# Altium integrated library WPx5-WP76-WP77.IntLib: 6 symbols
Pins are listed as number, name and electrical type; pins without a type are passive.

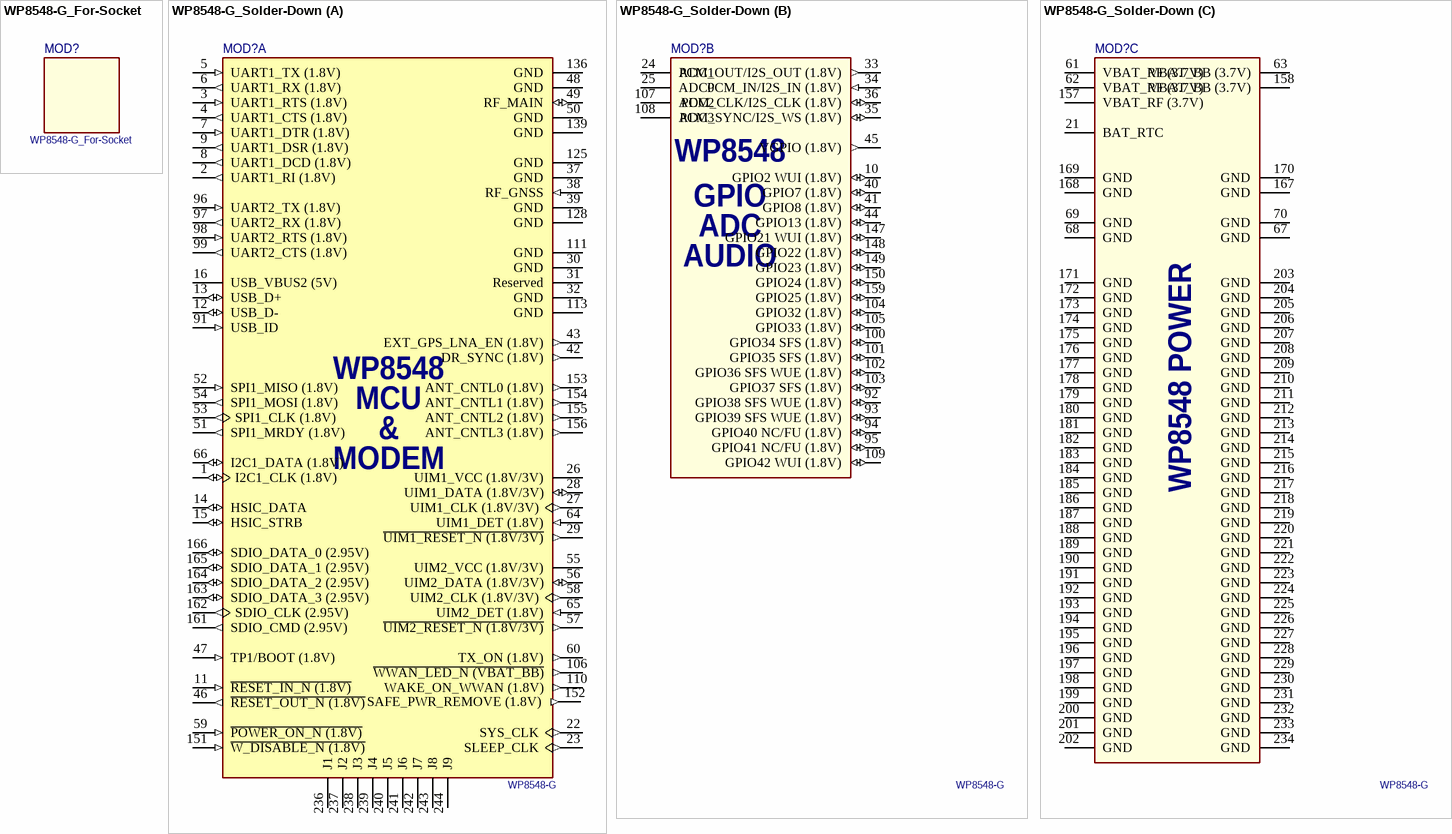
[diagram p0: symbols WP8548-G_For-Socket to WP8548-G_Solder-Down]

## WP8548-G_For-Socket
designator MOD?
Module Embedded MCU Wireless AirPrime WP8548 with GNSS; Manufacturer: Sierra Wireless; Description - Long: Sierra Wireless AirPrime WP8548 Smart Embedded Module with GNSS; Frequency GNSS: GPS 1575.42 ±1.023 MHz, GLONASS 1597.52–1605.92 MHz, Galileo 1575.42 ±2.046 MHz; Frequency GPRS/EDGE: GSM 850 Tx824–849 Rx869–894 MHz, E-GSM 900 Tx880–915 Rx925–960 MHz, DCS 1800 Tx1710–1785 Rx1805–1880 MHz, PCS 1900 Tx1850–1910 Rx1930–1990 MHz; Frequency UMTS: B1 Tx1920–1980 Rx2110–2170 MHz, B2 Tx1850–1910 Rx1930–1990 MHz, B5 Tx824–849 Rx869–894 MHz, B6 Tx830–840 Rx875–885 MHz, B8 Tx880–915 Rx925–960 MHz, B19 Tx830–845 Rx875–890 MHz; Functionality - MCU: 2 Cores: Qualcomm MDM8215 (QDSP6) for 2G/3G modem and ARM Cortex-A5 (550MHz) running Legato; Functionality - Radio: HSPA, WCDMA, Quad-band GSM, GPRS, EDGE (and GPS, GLONASS, Galileo on WP8548-G); Interface - ADC channels: 4x (ACD0-1 15-bit, ADC2-3 12-bit); Interface - Audio: 1x PCM (128/2048kHz) / I2S; Interface - GPIO: 20; Interface - HSIC (High-Speed Inter-Chip): 1x USB 2.0 Spec. V1.0; Interface - I2C: 1x 400kHz; Interface - SDIO: 1x 25MBps SD v2.0; Interface - SPI: 1x 4-wire @ 26MHz; Interface - UART: 1x 8-wire + 1x 4-wire @ 115200bps; Interface - UIM/SIM: 2x WCDMA & GSM11.11; Interface - USB: 1x 480Mbps; Memory - FLASH: 512MB; Memory - RAM: 256MB; Supply Current Max.: 3.0A; Supply Current Nom.: 1.0A; Supply Voltage Droop Max.: 250mV; Supply Voltage Max.: 4.3V; Supply Voltage Min.: 3.4V; Supply Voltage Nom.: 3.7V; Supply Voltage Ripple Max.: 100mVpp; Supply Voltage Transient Max.: 300mV; Temperature Max.: +85 deg C; Temperature Min.: -40 deg C; Release By: EDA Technologies; Release Revision: 1.2; Release Status: Released; Release History: 2017-03-14 1.2 Updated GPIO definitions. 2016-10-13 1.1 Updated_2016-09-05 1.0 First Release_2016-06-30 0.1 First Draft; Humidity Max.: 95% RH; Humidity Min.: 0% RH
footprint WP8548_For-Socket (LGA, 239 pads, Body 23.00 X 22.00 X 4.352mm)

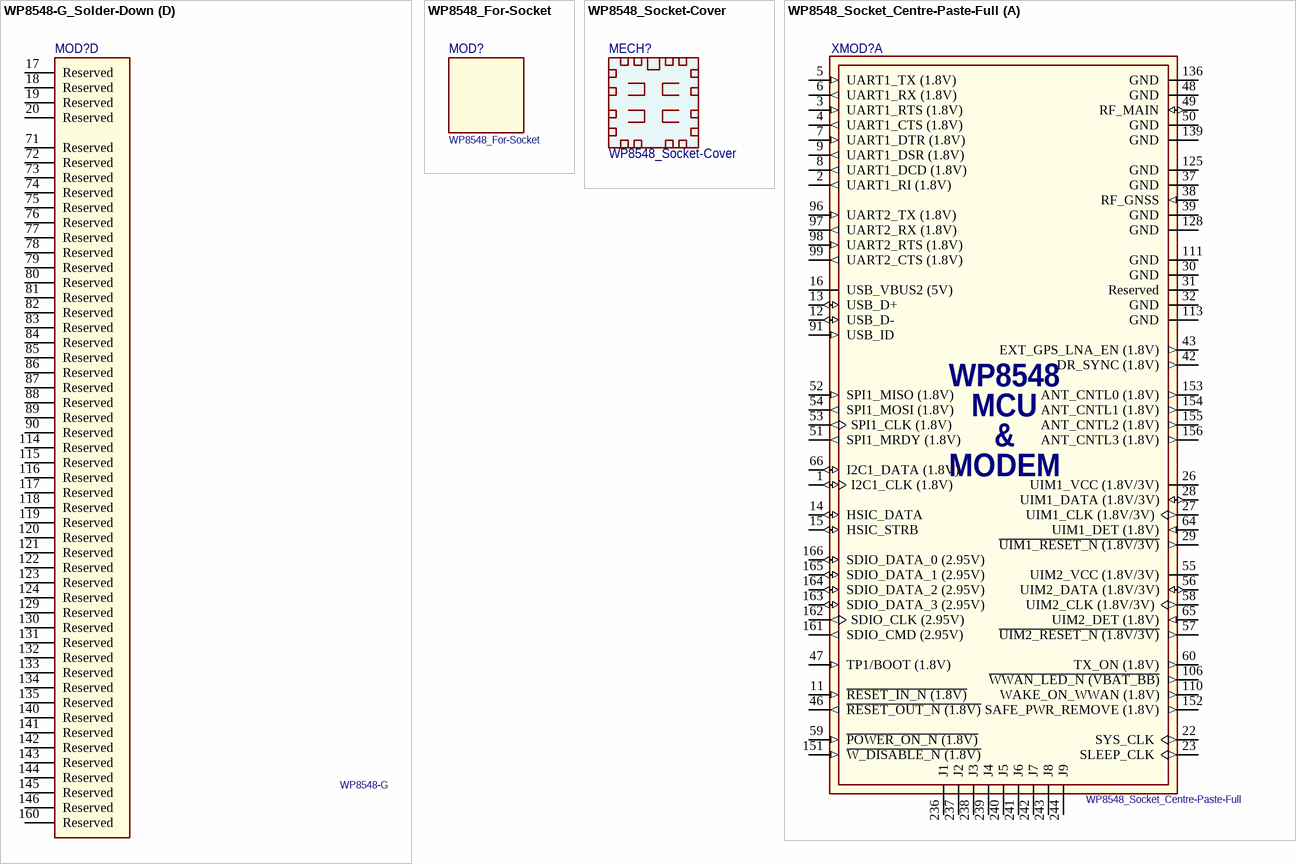
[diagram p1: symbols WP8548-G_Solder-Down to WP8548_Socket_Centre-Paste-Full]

## WP8548-G_Solder-Down
designator MOD?, comment WP8548-G
Module Embedded MCU Wireless AirPrime WP8548 with GNSS; Manufacturer: Sierra Wireless; Description - Long: Sierra Wireless AirPrime WP8548 Smart Embedded Module with GNSS; Frequency GNSS: GPS 1575.42 ±1.023 MHz, GLONASS 1597.52–1605.92 MHz, Galileo 1575.42 ±2.046 MHz; Frequency GPRS/EDGE: GSM 850 Tx824–849 Rx869–894 MHz, E-GSM 900 Tx880–915 Rx925–960 MHz, DCS 1800 Tx1710–1785 Rx1805–1880 MHz, PCS 1900 Tx1850–1910 Rx1930–1990 MHz; Frequency UMTS: B1 Tx1920–1980 Rx2110–2170 MHz, B2 Tx1850–1910 Rx1930–1990 MHz, B5 Tx824–849 Rx869–894 MHz, B6 Tx830–840 Rx875–885 MHz, B8 Tx880–915 Rx925–960 MHz, B19 Tx830–845 Rx875–890 MHz; Functionality - MCU: 2 Cores: Qualcomm MDM8215 (QDSP6) for 2G/3G modem and ARM Cortex-A5 (550MHz) running Legato; Functionality - Radio: HSPA, WCDMA, Quad-band GSM, GPRS, EDGE (and GPS, GLONASS, Galileo on WP8548-G); Interface - ADC channels: 4x (ACD0-1 15-bit, ADC2-3 12-bit); Interface - Audio: 1x PCM (128/2048kHz) / I2S; Interface - GPIO: 20; Interface - HSIC (High-Speed Inter-Chip): 1x USB 2.0 Spec. V1.0; Interface - I2C: 1x 400kHz; Interface - SDIO: 1x 25MBps SD v2.0; Interface - SPI: 1x 4-wire @ 26MHz; Interface - UART: 1x 8-wire + 1x 4-wire @ 115200bps; Interface - UIM/SIM: 2x WCDMA & GSM11.11; Interface - USB: 1x 480Mbps; Memory - FLASH: 512MB; Memory - RAM: 256MB; Supply Current Max.: 3.0A; Supply Current Nom.: 1.0A; Supply Voltage Droop Max.: 250mV; Supply Voltage Max.: 4.3V; Supply Voltage Min.: 3.4V; Supply Voltage Nom.: 3.7V; Supply Voltage Ripple Max.: 100mVpp; Supply Voltage Transient Max.: 300mV; Temperature Max.: +85 deg C; Temperature Min.: -40 deg C; Release By: EDA Technologies; Release Revision: 1.2; Release Status: Released; Release History: 2017-03-14 1.2 Updated GPIO definitions. 2016-10-13 1.1 Updated_2016-09-05 1.0 First Release_2016-06-30 0.1 First Draft; Humidity Max.: 95% RH; Humidity Min.: 0% RH
footprint WP8548_Solder-Down_LGA176_Large-Centre-Pad (LGA, 176 pads, Body 23.00 X 22.00 X 4.352mm, Large Centre Pad)
part A pins: 1 I2C1_CLK (1.8V) (io) "I2C Clock - 2k2 internal pull-up", 2 UART1_RI (1.8V) (out) "Ring Indicator. Signal incoming calls (voice and data), SMS, etc", 3 UART1_RTS (1.8V) (in) "Ready To Send, flow control", 4 UART1_CTS (1.8V) (out) "Clear To Send, flow control", 5 UART1_TX (1.8V) (in) "Transmit Data", 6 UART1_RX (1.8V) (out) "Receive Data", 7 UART1_DTR (1.8V) (in) "Data terminal ready. Prevents the AirPrime AirPrime WP8548 from entering sleep mode, switches between data mode and command mode, and wakes the module.", 8 UART1_DCD (1.8V) (out) "Data Carrier Detect. Signal data connection in progress", 9 UART1_DSR (1.8V) (out) "Data Set Ready. Signal UART interface is ON", 11 ~{RESET_IN_N (1.8V)} (in) "External Reset Input", 12 USB_D- (io) "Differential data interface negative", 13 USB_D+ (io) "Differential data interface positive", 14 HSIC_DATA (io) "HSIC data", 15 HSIC_STRB (io) "HSIC strobe signal", 16 USB_VBUS2 (5V) (power) "USB supply voltage input", 22 SYS_CLK (out) "19.2 MHz digital clock output", 23 SLEEP_CLK (out) "32.768 kHz digital clock output", 26 UIM1_VCC (1.8V/3V) (power) "Supply output", 27 UIM1_CLK (1.8V/3V) (out) "Clock", 28 UIM1_DATA (1.8V/3V) (io) "Data connection", 29 ~{UIM1_RESET_N (1.8V/3V)} (out) "Reset", 30 GND (power), 31 Reserved, 32 GND (power), 37 GND "GNSS Antenna Ground", 38 RF_GNSS (in) "GNSS Antenna Interface", 39 GND "GNSS Antenna Ground", 42 DR_SYNC (1.8V) (out) "GPS dead reckoning sync signal", 43 EXT_GPS_LNA_EN (1.8V) (out) "External GNSS LNA enable", 46 ~{RESET_OUT_N (1.8V)} (out) "Module reset peripheral device control", 47 TP1/BOOT (1.8V) (in) "Service (boot load)", 48 GND "Primary Antenna Ground", 49 RF_MAIN (io) "Primary Antenna Interface", 50 GND "Primary Antenna Ground", 51 SPI1_MRDY (1.8V) (out) "SPI Master Ready", 52 SPI1_MISO (1.8V) (in) "SPI Master Input/Slave Output", 53 SPI1_CLK (1.8V) (out) "SPI serial clock", 54 SPI1_MOSI (1.8V) (out) "SPI Master Output/Slave Input", 55 UIM2_VCC (1.8V/3V) (power) "Supply output", 56 UIM2_DATA (1.8V/3V) (io) "Data connection", 57 ~{UIM2_RESET_N (1.8V/3V)} (out) "Reset", 58 UIM2_CLK (1.8V/3V) (out) "Clock", 59 ~{POWER_ON_N (1.8V)} (in) "Power On control Signal", 60 TX_ON (1.8V) (out) "Tx activity indicator", 64 UIM1_DET (1.8V) (in) "Detect UIM", 65 UIM2_DET (1.8V) (in) "Detect UIM", 66 I2C1_DATA (1.8V) (io) "I2C Data - 2k2 internal pull-up", 91 USB_ID (in) "Used for USB_OTG", 96 UART2_TX (1.8V) (in) "Transmit data", 97 UART2_RX (1.8V) (out) "Receive data", 98 UART2_RTS (1.8V) (in) "Ready To Send, flow control", 99 UART2_CTS (1.8V) (out) "Clear To Send, flow control", 106 ~{WWAN_LED_N (VBAT_BB)} (out) "LED driver control", 110 WAKE_ON_WWAN (1.8V) (out) "Driven high to wake the hst when specific events occur", 111 GND (power), 113 GND (power), 125 GND "GNSS Antenna Ground", 128 GND "GNSS Antenna Ground", 136 GND "Primary Antenna Ground", 139 GND "Primary Antenna Ground", 151 ~{W_DISABLE_N (1.8V)} (in) "Wireless Disable", 152 SAFE_PWR_REMOVE (1.8V) (out) "Indicate to host that main DC power can be removed", 153 ANT_CNTL0 (1.8V) (out) "Customer-defined external switch control for tunable antennas", 154 ANT_CNTL1 (1.8V) (out) "Customer-defined external switch control for tunable antennas", 155 ANT_CNTL2 (1.8V) (out) "Customer-defined external switch control for tunable antennas", 156 ANT_CNTL3 (1.8V) (out) "Customer-defined external switch control for tunable antennas", 161 SDIO_CMD (2.95V) (out) "SDIO command", 162 SDIO_CLK (2.95V) (out) "SDIO clock", 163 SDIO_DATA_3 (2.95V) (io) "SDIO data bit 3", 164 SDIO_DATA_2 (2.95V) (io) "SDIO data bit 2", 165 SDIO_DATA_1 (2.95V) (io) "SDIO data bit 1", 166 SDIO_DATA_0 (2.95V) (io) "SDIO data bit 0", 236 J1 "Test Point", 237 J2 "Test Point", 238 J3 "Test Point", 239 J4 "Test Point", 240 J5 "Test Point", 241 J6 "Test Point", 242 J7 "Test Point", 243 J8 "Test Point", 244 J9 "Test Point"
part B pins: 10 GPIO2 WUI (1.8V) (io) "General purpose I/O (Wakeup Interrupt)", 24 ADC1 "Analog to Digital Converter", 25 ADC0 "Analog to Digital Converter", 33 PCM_OUT/I2S_OUT (1.8V) (out) "PCM/I2S Data Out", 34 PCM_IN/I2S_IN (1.8V) (in) "PCM/I2S Data In", 35 PCM_SYNC/I2S_WS (1.8V) (io) "PCM Sync/I2S Word Select", 36 PCM_CLK/I2S_CLK (1.8V) (io) "PCM/I2S Clock", 40 GPIO7 (1.8V) (io) "General purpose I/O", 41 GPIO8 (1.8V) (io) "General purpose I/O", 44 GPIO13 (1.8V) (io) "General purpose I/O", 45 VGPIO (1.8V) (out) "GPIO voltage output", 92 GPIO38 SFS WUE (1.8V) (io) "General purpose I/O (SYSFS Wakeup Event)", 93 GPIO39 SFS WUE (1.8V) (io) "General purpose I/O (SYSFS Wakeup Event)", 94 GPIO40 NC/FU (1.8V) (io) "General purpose I/O (Do Not Use/Future Use)", 95 GPIO41 NC/FU (1.8V) (io) "General purpose I/O (Do Not Use/Future Use)", 100 GPIO34 SFS (1.8V) (io) "General purpose I/O (SYSFS)", 101 GPIO35 SFS (1.8V) (io) "General purpose I/O (SYSFS)", 102 GPIO36 SFS WUE (1.8V) (io) "General purpose I/O (SYSFS Wakeup Event)", 103 GPIO37 SFS (1.8V) (io) "General purpose I/O (SYSFS)", 104 GPIO32 (1.8V) (io) "General purpose I/O", 105 GPIO33 (1.8V) (io) "General purpose I/O", 107 ADC2 "Analog to Digital Converter", 108 ADC3 "Analog to Digital Converter", 109 GPIO42 WUI (1.8V) (io) "General purpose I/O (Wakeup Interrupt)", 147 GPIO21 WUI (1.8V) (io) "General purpose I/O (Wakeup Interrupt)", 148 GPIO22 (1.8V) (io) "General purpose I/O", 149 GPIO23 (1.8V) (io) "General purpose I/O", 150 GPIO24 (1.8V) (io) "General purpose I/O", 159 GPIO25 (1.8V) (io) "General purpose I/O"
part C pins: 21 BAT_RTC (power) "Voltage input/Charging output", 61 VBAT_RF (3.7V) (power) "RF power supply", 62 VBAT_RF (3.7V) (power) "RF power supply", 63 VBAT_BB (3.7V) (power) "Baseband power supply", 67 GND (power), 68 GND (power), 69 GND (power), 70 GND (power), 157 VBAT_RF (3.7V) (power) "RF power supply", 158 VBAT_BB (3.7V) (power) "Baseband power supply", 167 GND (power), 168 GND (power), 169 GND (power), 170 GND (power), 171 GND (power), 172 GND (power), 173 GND (power), 174 GND (power), 175 GND (power), 176 GND (power), 177 GND (power), 178 GND (power), 179 GND (power), 180 GND (power), 181 GND (power), 182 GND (power), 183 GND (power), 184 GND (power), 185 GND (power), 186 GND (power), 187 GND (power), 188 GND (power), 189 GND (power), 190 GND (power), 191 GND (power), 192 GND (power), 193 GND (power), 194 GND (power), 195 GND (power), 196 GND (power), 197 GND (power), 198 GND (power), 199 GND (power), 200 GND (power), 201 GND (power), 202 GND (power), 203 GND (power), 204 GND (power), 205 GND (power), 206 GND (power), 207 GND (power), 208 GND (power), 209 GND (power), 210 GND (power), 211 GND (power), 212 GND (power), 213 GND (power), 214 GND (power), 215 GND (power), 216 GND (power), 217 GND (power), 218 GND (power), 219 GND (power), 220 GND (power), 221 GND (power), 222 GND (power), 223 GND (power), 224 GND (power), 225 GND (power), 226 GND (power), 227 GND (power), 228 GND (power), 229 GND (power), 230 GND (power), 231 GND (power), 232 GND (power), 233 GND (power), 234 GND (power)
part D pins: 17 Reserved, 18 Reserved, 19 Reserved, 20 Reserved, 71 Reserved, 72 Reserved, 73 Reserved, 74 Reserved, 75 Reserved, 76 Reserved, 77 Reserved, 78 Reserved, 79 Reserved, 80 Reserved, 81 Reserved, 82 Reserved, 83 Reserved, 84 Reserved, 85 Reserved, 86 Reserved, 87 Reserved, 88 Reserved, 89 Reserved, 90 Reserved, 114 Reserved, 115 Reserved, 116 Reserved, 117 Reserved, 118 Reserved, 119 Reserved, 120 Reserved, 121 Reserved, 122 Reserved, 123 Reserved, 124 Reserved, 129 Reserved, 130 Reserved, 131 Reserved, 132 Reserved, 133 Reserved, 134 Reserved, 135 Reserved, 140 Reserved, 141 Reserved, 142 Reserved, 143 Reserved, 144 Reserved, 145 Reserved, 146 Reserved, 160 Reserved

## WP8548_For-Socket
designator MOD?
Module Embedded MCU Wireless AirPrime WP8548 without GNSS; Manufacturer: Sierra Wireless; Description - Long: Sierra Wireless AirPrime WP8548 Smart Embedded Module; Frequency GNSS: Available on WP8548-G; Frequency GPRS/EDGE: GSM 850 Tx824–849 Rx869–894 MHz, E-GSM 900 Tx880–915 Rx925–960 MHz, DCS 1800 Tx1710–1785 Rx1805–1880 MHz, PCS 1900 Tx1850–1910 Rx1930–1990 MHz; Frequency UMTS: B1 Tx1920–1980 Rx2110–2170 MHz, B2 Tx1850–1910 Rx1930–1990 MHz, B5 Tx824–849 Rx869–894 MHz, B6 Tx830–840 Rx875–885 MHz, B8 Tx880–915 Rx925–960 MHz, B19 Tx830–845 Rx875–890 MHz; Functionality - MCU: 2 Cores: Qualcomm MDM8215 (QDSP6) for 2G/3G modem and ARM Cortex-A5 (550MHz) running Legato; Functionality - Radio: HSPA, WCDMA, Quad-band GSM, GPRS, EDGE (and GPS, GLONASS, Galileo on WP8548-G); Interface - ADC channels: 4x (ACD0-1 15-bit, ADC2-3 12-bit); Interface - Audio: 1x PCM (128/2048kHz) / I2S; Interface - GPIO: 20; Interface - HSIC (High-Speed Inter-Chip): 1x USB 2.0 Spec. V1.0; Interface - I2C: 1x 400kHz; Interface - SDIO: 1x 25MBps SD v2.0; Interface - SPI: 1x 4-wire @ 26MHz; Release By: EDA Technologies; Release Revision: 1.2; Release Status: Released; Memory - FLASH: 512MB; Memory - RAM: 256MB; Supply Current Max.: 3.0A; Supply Current Nom.: 1.0A; Supply Voltage Droop Max.: 250mV; Supply Voltage Max.: 4.3V; Supply Voltage Min.: 3.4V; Supply Voltage Nom.: 3.7V; Supply Voltage Ripple Max.: 100mVpp; Supply Voltage Transient Max.: 300mV; Temperature Max.: +85 deg C; Temperature Min.: -40 deg C; Interface - UART: 1x 8-wire + 1x 4-wire @ 115200bps; Interface - UIM/SIM: 2x WCDMA & GSM11.11; Interface - USB: 1x 480Mbps; Release History: 2017-03-14 1.2 Updated GPIO definitions. 2016-10-13 1.1 Updated_2016-09-05 1.0 First Release_2016-06-30 0.1 First Draft; Humidity Max.: 95% RH; Humidity Min.: 0% RH
footprint WP8548_For-Socket (LGA, 239 pads, Body 23.00 X 22.00 X 4.352mm)

## WP8548_Socket-Cover
designator MECH?
Mechanical Cover for WP8548 Socket; Manufacturer: Sierra Wireless; Manufacturer Part Number: 6000637; Release By: EDA Technologies; Release Status: Released; Release Revision: 1.2; Description - Long: Sierra Wireless AirPrime WP Snap-in Socket Cover; Release History: 2017-03-14 1.2 Updated GPIO definitions. 2016-10-13 1.1 Updated_2016-09-05 1.0 First Release_2016-06-30 0.1 First Draft; Temperature Max.: +85 deg C; Temperature Min.: -40 deg C; Humidity Max.: 70% RH; Humidity Min.: 15% RH
footprint WP8548_Socket-Cover (Cover Clip-on for WP8548 Socket, Body 27.40 x 26.40 x 6.90mm, height from board to top)

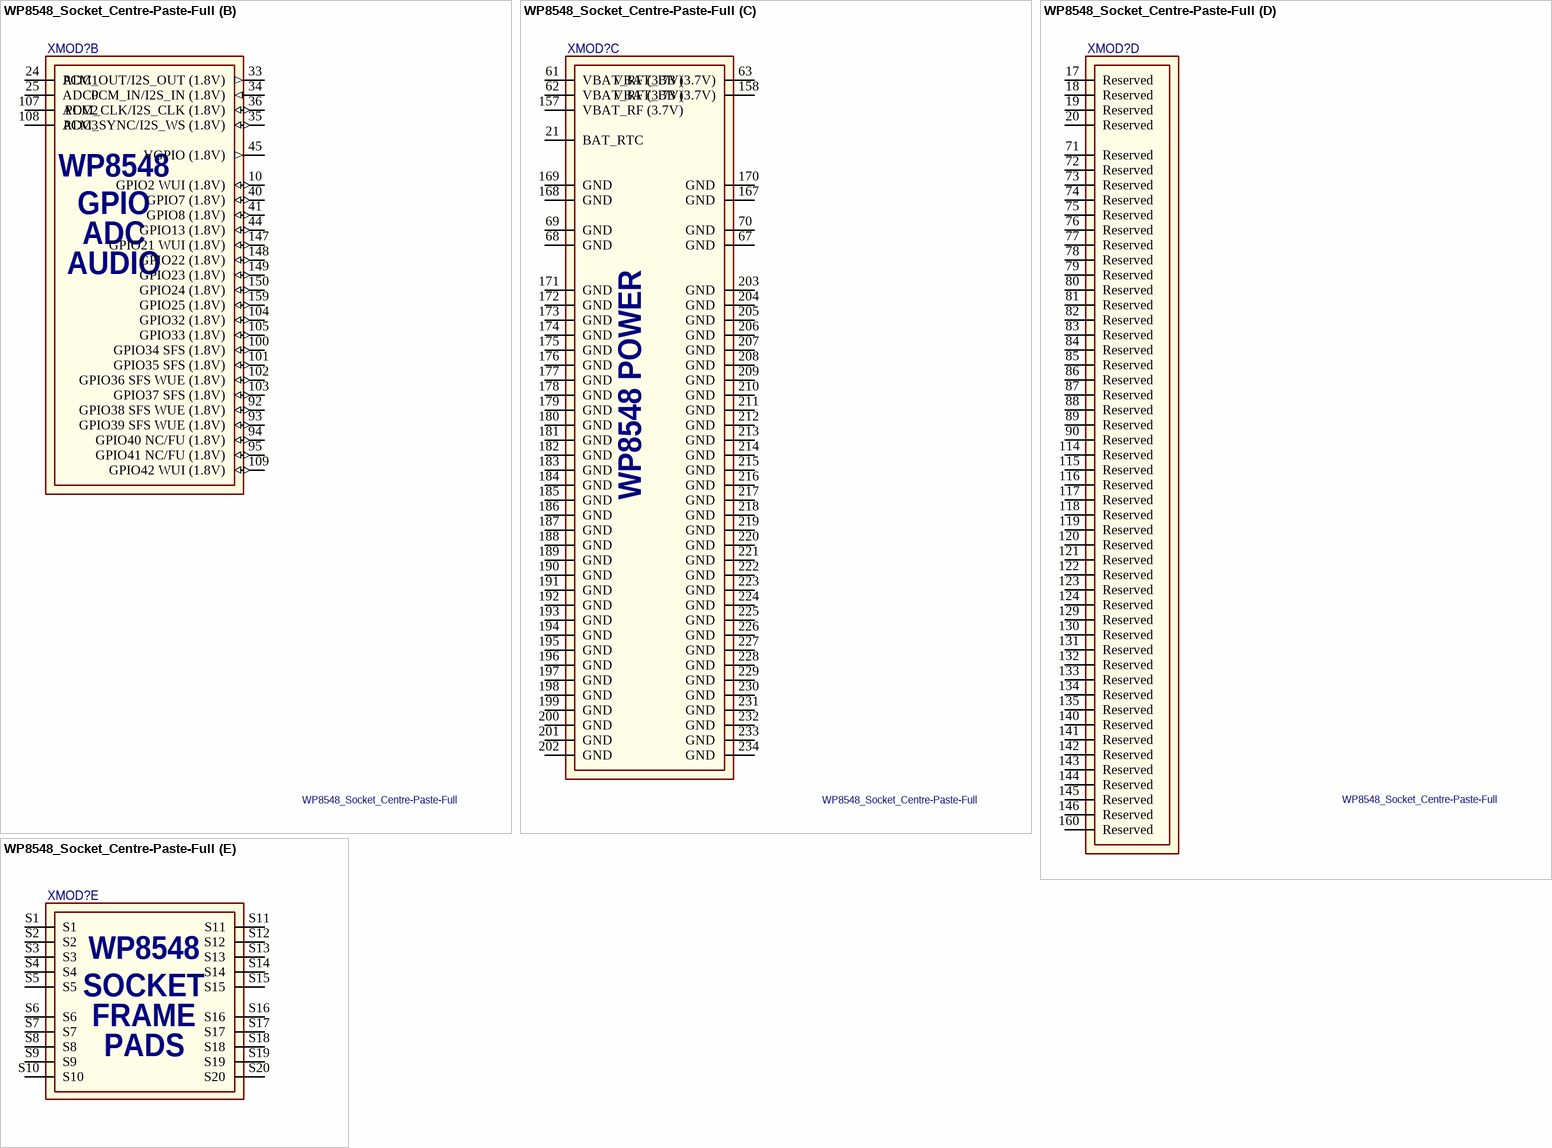
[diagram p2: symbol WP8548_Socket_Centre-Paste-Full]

## WP8548_Socket_Centre-Paste-Full
designator XMOD?
Socket for WP8548 or WP8548-G; Manufacturer: Sierra Wireless; Manufacturer Part Number: 6000636; Description - Long: Sierra Wireless AirPrime WP Snap-in Socket; Temperature Max.: +85 deg C; Temperature Min.: -40 deg C; Release By: EDA Technologies; Release History: 2017-03-14 1.2 Updated GPIO definitions. 2016-10-13 1.1 Updated_2016-09-05 1.0 First Release_2016-06-30 0.1 First Draft; Release Revision: 1.2; Release Status: Released; Humidity Max.: 70% RH; Humidity Min.: 15% RH
footprint WP8548_Socket-Dual_LGA196_With-Centre-Paste (LGA, 197 Pads, Body 23.00 X 22.00 X 6.9mm, With Centre Paste Mask)
part A pins: 1 I2C1_CLK (1.8V) (io) "I2C Clock - 2k2 internal pull-up", 2 UART1_RI (1.8V) (out) "Ring Indicator. Signal incoming calls (voice and data), SMS, etc", 3 UART1_RTS (1.8V) (in) "Ready To Send, flow control", 4 UART1_CTS (1.8V) (out) "Clear To Send, flow control", 5 UART1_TX (1.8V) (in) "Transmit Data", 6 UART1_RX (1.8V) (out) "Receive Data", 7 UART1_DTR (1.8V) (in) "Data terminal ready. Prevents the AirPrime AirPrime WP8548 from entering sleep mode, switches between data mode and command mode, and wakes the module.", 8 UART1_DCD (1.8V) (out) "Data Carrier Detect. Signal data connection in progress", 9 UART1_DSR (1.8V) (out) "Data Set Ready. Signal UART interface is ON", 11 ~{RESET_IN_N (1.8V)} (in) "External Reset Input", 12 USB_D- (io) "Differential data interface negative", 13 USB_D+ (io) "Differential data interface positive", 14 HSIC_DATA (io) "HSIC data", 15 HSIC_STRB (io) "HSIC strobe signal", 16 USB_VBUS2 (5V) (power) "USB supply voltage input", 22 SYS_CLK (out) "19.2 MHz digital clock output", 23 SLEEP_CLK (out) "32.768 kHz digital clock output", 26 UIM1_VCC (1.8V/3V) (power) "Supply output", 27 UIM1_CLK (1.8V/3V) (out) "Clock", 28 UIM1_DATA (1.8V/3V) (io) "Data connection", 29 ~{UIM1_RESET_N (1.8V/3V)} (out) "Reset", 30 GND (power), 31 Reserved, 32 GND (power), 37 GND "GNSS Antenna Ground", 38 RF_GNSS (in) "GNSS Antenna Interface", 39 GND "GNSS Antenna Ground", 42 DR_SYNC (1.8V) (out) "GPS dead reckoning sync signal", 43 EXT_GPS_LNA_EN (1.8V) (out) "External GNSS LNA enable", 46 ~{RESET_OUT_N (1.8V)} (out) "Module reset peripheral device control", 47 TP1/BOOT (1.8V) (in) "Service (boot load)", 48 GND "Primary Antenna Ground", 49 RF_MAIN (io) "Primary Antenna Interface", 50 GND "Primary Antenna Ground", 51 SPI1_MRDY (1.8V) (out) "SPI Master Ready", 52 SPI1_MISO (1.8V) (in) "SPI Master Input/Slave Output", 53 SPI1_CLK (1.8V) (out) "SPI serial clock", 54 SPI1_MOSI (1.8V) (out) "SPI Master Output/Slave Input", 55 UIM2_VCC (1.8V/3V) (power) "Supply output", 56 UIM2_DATA (1.8V/3V) (io) "Data connection", 57 ~{UIM2_RESET_N (1.8V/3V)} (out) "Reset", 58 UIM2_CLK (1.8V/3V) (out) "Clock", 59 ~{POWER_ON_N (1.8V)} (in) "Power On control Signal", 60 TX_ON (1.8V) (out) "Tx activity indicator", 64 UIM1_DET (1.8V) (in) "Detect UIM", 65 UIM2_DET (1.8V) (in) "Detect UIM", 66 I2C1_DATA (1.8V) (io) "I2C Data - 2k2 internal pull-up", 91 USB_ID (in) "Used for USB_OTG", 96 UART2_TX (1.8V) (in) "Transmit data", 97 UART2_RX (1.8V) (out) "Receive data", 98 UART2_RTS (1.8V) (in) "Ready To Send, flow control", 99 UART2_CTS (1.8V) (out) "Clear To Send, flow control", 106 ~{WWAN_LED_N (VBAT_BB)} (out) "LED driver control", 110 WAKE_ON_WWAN (1.8V) (out) "Driven high to wake the hst when specific events occur", 111 GND (power), 113 GND (power), 125 GND "GNSS Antenna Ground", 128 GND "GNSS Antenna Ground", 136 GND "Primary Antenna Ground", 139 GND "Primary Antenna Ground", 151 ~{W_DISABLE_N (1.8V)} (in) "Wireless Disable", 152 SAFE_PWR_REMOVE (1.8V) (out) "Indicate to host that main DC power can be removed", 153 ANT_CNTL0 (1.8V) (out) "Customer-defined external switch control for tunable antennas", 154 ANT_CNTL1 (1.8V) (out) "Customer-defined external switch control for tunable antennas", 155 ANT_CNTL2 (1.8V) (out) "Customer-defined external switch control for tunable antennas", 156 ANT_CNTL3 (1.8V) (out) "Customer-defined external switch control for tunable antennas", 161 SDIO_CMD (2.95V) (out) "SDIO command", 162 SDIO_CLK (2.95V) (out) "SDIO clock", 163 SDIO_DATA_3 (2.95V) (io) "SDIO data bit 3", 164 SDIO_DATA_2 (2.95V) (io) "SDIO data bit 2", 165 SDIO_DATA_1 (2.95V) (io) "SDIO data bit 1", 166 SDIO_DATA_0 (2.95V) (io) "SDIO data bit 0", 236 J1 "Test Point", 237 J2 "Test Point", 238 J3 "Test Point", 239 J4 "Test Point", 240 J5 "Test Point", 241 J6 "Test Point", 242 J7 "Test Point", 243 J8 "Test Point", 244 J9 "Test Point"
part B pins: 10 GPIO2 WUI (1.8V) (io) "General purpose I/O (Wakeup Interrupt)", 24 ADC1 "Analog to Digital Converter", 25 ADC0 "Analog to Digital Converter", 33 PCM_OUT/I2S_OUT (1.8V) (out) "PCM/I2S Data Out", 34 PCM_IN/I2S_IN (1.8V) (in) "PCM/I2S Data In", 35 PCM_SYNC/I2S_WS (1.8V) (io) "PCM Sync/I2S Word Select", 36 PCM_CLK/I2S_CLK (1.8V) (io) "PCM/I2S Clock", 40 GPIO7 (1.8V) (io) "General purpose I/O", 41 GPIO8 (1.8V) (io) "General purpose I/O", 44 GPIO13 (1.8V) (io) "General purpose I/O", 45 VGPIO (1.8V) (out) "GPIO voltage output", 92 GPIO38 SFS WUE (1.8V) (io) "General purpose I/O (SYSFS Wakeup Event)", 93 GPIO39 SFS WUE (1.8V) (io) "General purpose I/O (SYSFS Wakeup Event)", 94 GPIO40 NC/FU (1.8V) (io) "General purpose I/O (Do Not Use/Future Use)", 95 GPIO41 NC/FU (1.8V) (io) "General purpose I/O (Do Not Use/Future Use)", 100 GPIO34 SFS (1.8V) (io) "General purpose I/O (SYSFS)", 101 GPIO35 SFS (1.8V) (io) "General purpose I/O (SYSFS)", 102 GPIO36 SFS WUE (1.8V) (io) "General purpose I/O (SYSFS Wakeup Event)", 103 GPIO37 SFS (1.8V) (io) "General purpose I/O (SYSFS)", 104 GPIO32 (1.8V) (io) "General purpose I/O", 105 GPIO33 (1.8V) (io) "General purpose I/O", 107 ADC2 "Analog to Digital Converter", 108 ADC3 "Analog to Digital Converter", 109 GPIO42 WUI (1.8V) (io) "General purpose I/O (Wakeup Interrupt)", 147 GPIO21 WUI (1.8V) (io) "General purpose I/O (Wakeup Interrupt)", 148 GPIO22 (1.8V) (io) "General purpose I/O", 149 GPIO23 (1.8V) (io) "General purpose I/O", 150 GPIO24 (1.8V) (io) "General purpose I/O", 159 GPIO25 (1.8V) (io) "General purpose I/O"
part C pins: 21 BAT_RTC (power) "Voltage input/Charging output", 61 VBAT_RF (3.7V) (power) "RF power supply", 62 VBAT_RF (3.7V) (power) "RF power supply", 63 VBAT_BB (3.7V) (power) "Baseband power supply", 67 GND (power), 68 GND (power), 69 GND (power), 70 GND (power), 157 VBAT_RF (3.7V) (power) "RF power supply", 158 VBAT_BB (3.7V) (power) "Baseband power supply", 167 GND (power), 168 GND (power), 169 GND (power), 170 GND (power), 171 GND (power), 172 GND (power), 173 GND (power), 174 GND (power), 175 GND (power), 176 GND (power), 177 GND (power), 178 GND (power), 179 GND (power), 180 GND (power), 181 GND (power), 182 GND (power), 183 GND (power), 184 GND (power), 185 GND (power), 186 GND (power), 187 GND (power), 188 GND (power), 189 GND (power), 190 GND (power), 191 GND (power), 192 GND (power), 193 GND (power), 194 GND (power), 195 GND (power), 196 GND (power), 197 GND (power), 198 GND (power), 199 GND (power), 200 GND (power), 201 GND (power), 202 GND (power), 203 GND (power), 204 GND (power), 205 GND (power), 206 GND (power), 207 GND (power), 208 GND (power), 209 GND (power), 210 GND (power), 211 GND (power), 212 GND (power), 213 GND (power), 214 GND (power), 215 GND (power), 216 GND (power), 217 GND (power), 218 GND (power), 219 GND (power), 220 GND (power), 221 GND (power), 222 GND (power), 223 GND (power), 224 GND (power), 225 GND (power), 226 GND (power), 227 GND (power), 228 GND (power), 229 GND (power), 230 GND (power), 231 GND (power), 232 GND (power), 233 GND (power), 234 GND (power)
part D pins: 17 Reserved, 18 Reserved, 19 Reserved, 20 Reserved, 71 Reserved, 72 Reserved, 73 Reserved, 74 Reserved, 75 Reserved, 76 Reserved, 77 Reserved, 78 Reserved, 79 Reserved, 80 Reserved, 81 Reserved, 82 Reserved, 83 Reserved, 84 Reserved, 85 Reserved, 86 Reserved, 87 Reserved, 88 Reserved, 89 Reserved, 90 Reserved, 114 Reserved, 115 Reserved, 116 Reserved, 117 Reserved, 118 Reserved, 119 Reserved, 120 Reserved, 121 Reserved, 122 Reserved, 123 Reserved, 124 Reserved, 129 Reserved, 130 Reserved, 131 Reserved, 132 Reserved, 133 Reserved, 134 Reserved, 135 Reserved, 140 Reserved, 141 Reserved, 142 Reserved, 143 Reserved, 144 Reserved, 145 Reserved, 146 Reserved, 160 Reserved
part E pins: S1 "Socket Frame Pad. Connect to Ground.", S2 "Socket Frame Pad. Connect to Ground.", S3 "Socket Frame Pad. Connect to Ground.", S4 "Socket Frame Pad. Connect to Ground.", S5 "Socket Frame Pad. Connect to Ground.", S6 "Socket Frame Pad. Connect to Ground.", S7 "Socket Frame Pad. Connect to Ground.", S8 "Socket Frame Pad. Connect to Ground.", S9 "Socket Frame Pad. Connect to Ground.", S10 "Socket Frame Pad. Connect to Ground.", S11 "Socket Frame Pad. Connect to Ground.", S12 "Socket Frame Pad. Connect to Ground.", S13 "Socket Frame Pad. Connect to Ground.", S14 "Socket Frame Pad. Connect to Ground.", S15 "Socket Frame Pad. Connect to Ground.", S16 "Socket Frame Pad. Connect to Ground.", S17 "Socket Frame Pad. Connect to Ground.", S18 "Socket Frame Pad. Connect to Ground.", S19 "Socket Frame Pad. Connect to Ground.", S20 "Socket Frame Pad. Connect to Ground."

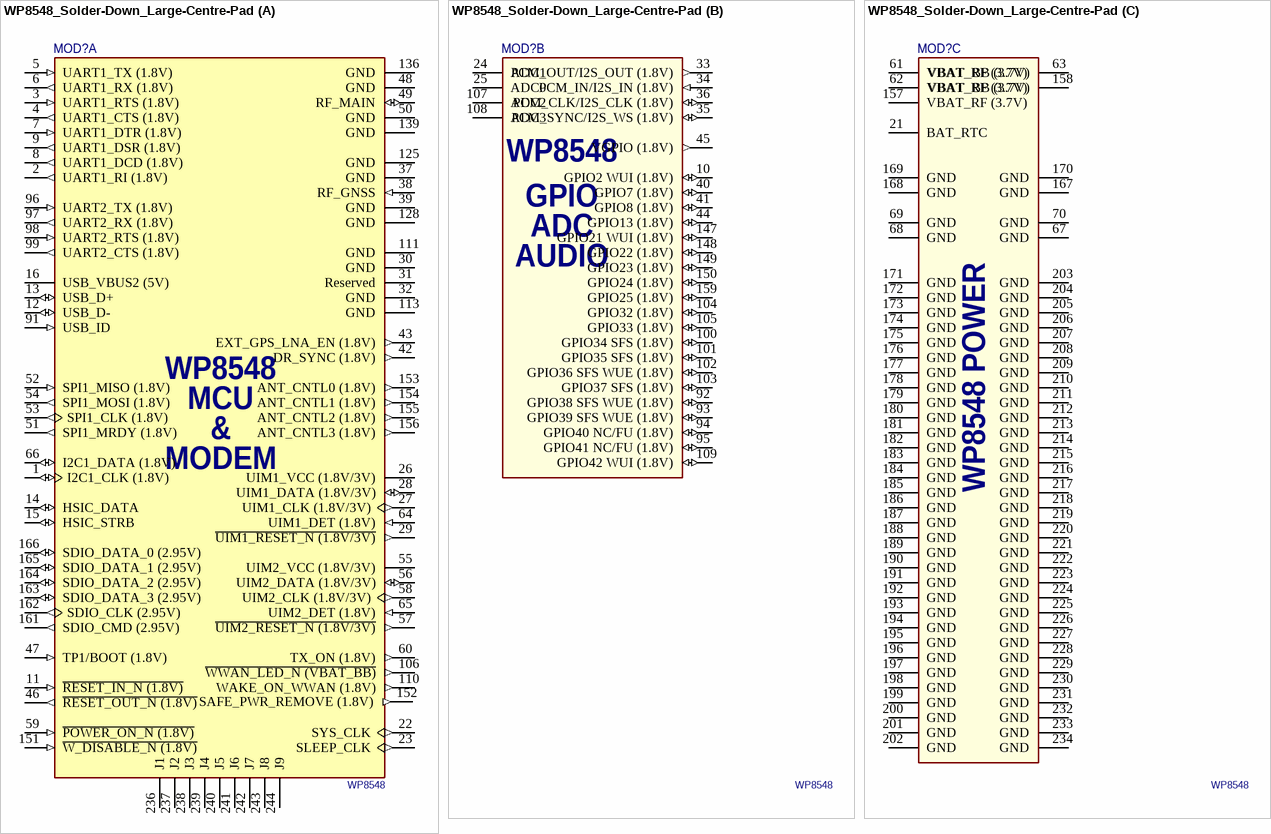
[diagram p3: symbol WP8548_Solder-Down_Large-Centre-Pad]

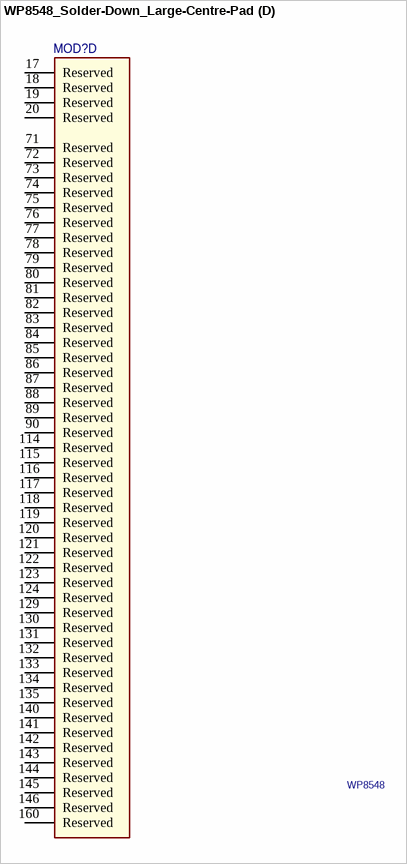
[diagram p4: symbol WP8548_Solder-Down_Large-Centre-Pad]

## WP8548_Solder-Down_Large-Centre-Pad
designator MOD?, comment WP8548
Module Embedded MCU Wireless AirPrime WP8548 without GNSS; Manufacturer: Sierra Wireless; Description - Long: Sierra Wireless AirPrime WP8548 Smart Embedded Module; Frequency GNSS: Available on WP8548-G; Frequency GPRS/EDGE: GSM 850 Tx824–849 Rx869–894 MHz, E-GSM 900 Tx880–915 Rx925–960 MHz, DCS 1800 Tx1710–1785 Rx1805–1880 MHz, PCS 1900 Tx1850–1910 Rx1930–1990 MHz; Frequency UMTS: B1 Tx1920–1980 Rx2110–2170 MHz, B2 Tx1850–1910 Rx1930–1990 MHz, B5 Tx824–849 Rx869–894 MHz, B6 Tx830–840 Rx875–885 MHz, B8 Tx880–915 Rx925–960 MHz, B19 Tx830–845 Rx875–890 MHz; Functionality - MCU: 2 Cores: Qualcomm MDM8215 (QDSP6) for 2G/3G modem and ARM Cortex-A5 (550MHz) running Legato; Functionality - Radio: HSPA, WCDMA, Quad-band GSM, GPRS, EDGE (and GPS, GLONASS, Galileo on WP8548-G); Interface - ADC channels: 4x (ACD0-1 15-bit, ADC2-3 12-bit); Interface - Audio: 1x PCM (128/2048kHz) / I2S; Interface - GPIO: 20; Interface - HSIC (High-Speed Inter-Chip): 1x USB 2.0 Spec. V1.0; Interface - I2C: 1x 400kHz; Interface - SDIO: 1x 25MBps SD v2.0; Interface - SPI: 1x 4-wire @ 26MHz; Interface - UART: 1x 8-wire + 1x 4-wire @ 115200bps; Interface - UIM/SIM: 2x WCDMA & GSM11.11; Interface - USB: 1x 480Mbps; Memory - FLASH: 512MB; Memory - RAM: 256MB; Supply Current Max.: 3.0A; Supply Current Nom.: 1.0A; Supply Voltage Droop Max.: 250mV; Supply Voltage Max.: 4.3V; Supply Voltage Min.: 3.4V; Supply Voltage Nom.: 3.7V; Supply Voltage Ripple Max.: 100mVpp; Supply Voltage Transient Max.: 300mV; Temperature Max.: +85 deg C; Temperature Min.: -40 deg C; Release By: EDA Technologies; Release History: 2017-03-14 1.2 Updated GPIO definitions. 2016-10-13 1.1 Updated_2016-09-05 1.0 First Release_2016-06-30 0.1 First Draft; Release Revision: 1.2; Release Status: Released; Humidity Max.: 95% RH; Humidity Min.: 0% RH
footprint WP8548_Solder-Down_LGA176_Large-Centre-Pad (LGA, 176 pads, Body 23.00 X 22.00 X 4.352mm, Large Centre Pad)
part A pins: 1 I2C1_CLK (1.8V) (io) "I2C Clock - 2k2 internal pull-up", 2 UART1_RI (1.8V) (out) "Ring Indicator. Signal incoming calls (voice and data), SMS, etc", 3 UART1_RTS (1.8V) (in) "Ready To Send, flow control", 4 UART1_CTS (1.8V) (out) "Clear To Send, flow control", 5 UART1_TX (1.8V) (in) "Transmit Data", 6 UART1_RX (1.8V) (out) "Receive Data", 7 UART1_DTR (1.8V) (in) "Data terminal ready. Prevents the AirPrime AirPrime WP8548 from entering sleep mode, switches between data mode and command mode, and wakes the module.", 8 UART1_DCD (1.8V) (out) "Data Carrier Detect. Signal data connection in progress", 9 UART1_DSR (1.8V) (out) "Data Set Ready. Signal UART interface is ON", 11 ~{RESET_IN_N (1.8V)} (in) "External Reset Input", 12 USB_D- (io) "Differential data interface negative", 13 USB_D+ (io) "Differential data interface positive", 14 HSIC_DATA (io) "HSIC data", 15 HSIC_STRB (io) "HSIC strobe signal", 16 USB_VBUS2 (5V) (power) "USB supply voltage input", 22 SYS_CLK (out) "19.2 MHz digital clock output", 23 SLEEP_CLK (out) "32.768 kHz digital clock output", 26 UIM1_VCC (1.8V/3V) (power) "Supply output", 27 UIM1_CLK (1.8V/3V) (out) "Clock", 28 UIM1_DATA (1.8V/3V) (io) "Data connection", 29 ~{UIM1_RESET_N (1.8V/3V)} (out) "Reset", 30 GND (power), 31 Reserved, 32 GND (power), 37 GND "GNSS Antenna Ground", 38 RF_GNSS (in) "GNSS Antenna Interface", 39 GND "GNSS Antenna Ground", 42 DR_SYNC (1.8V) (out) "GPS dead reckoning sync signal", 43 EXT_GPS_LNA_EN (1.8V) (out) "External GNSS LNA enable", 46 ~{RESET_OUT_N (1.8V)} (out) "Module reset peripheral device control", 47 TP1/BOOT (1.8V) (in) "Service (boot load)", 48 GND "Primary Antenna Ground", 49 RF_MAIN (io) "Primary Antenna Interface", 50 GND "Primary Antenna Ground", 51 SPI1_MRDY (1.8V) (out) "SPI Master Ready", 52 SPI1_MISO (1.8V) (in) "SPI Master Input/Slave Output", 53 SPI1_CLK (1.8V) (out) "SPI serial clock", 54 SPI1_MOSI (1.8V) (out) "SPI Master Output/Slave Input", 55 UIM2_VCC (1.8V/3V) (power) "Supply output", 56 UIM2_DATA (1.8V/3V) (io) "Data connection", 57 ~{UIM2_RESET_N (1.8V/3V)} (out) "Reset", 58 UIM2_CLK (1.8V/3V) (out) "Clock", 59 ~{POWER_ON_N (1.8V)} (in) "Power On control Signal", 60 TX_ON (1.8V) (out) "Tx activity indicator", 64 UIM1_DET (1.8V) (in) "Detect UIM", 65 UIM2_DET (1.8V) (in) "Detect UIM", 66 I2C1_DATA (1.8V) (io) "I2C Data - 2k2 internal pull-up", 91 USB_ID (in) "Used for USB_OTG", 96 UART2_TX (1.8V) (in) "Transmit data", 97 UART2_RX (1.8V) (out) "Receive data", 98 UART2_RTS (1.8V) (in) "Ready To Send, flow control", 99 UART2_CTS (1.8V) (out) "Clear To Send, flow control", 106 ~{WWAN_LED_N (VBAT_BB)} (out) "LED driver control", 110 WAKE_ON_WWAN (1.8V) (out) "Driven high to wake the hst when specific events occur", 111 GND (power), 113 GND (power), 125 GND "GNSS Antenna Ground", 128 GND "GNSS Antenna Ground", 136 GND "Primary Antenna Ground", 139 GND "Primary Antenna Ground", 151 ~{W_DISABLE_N (1.8V)} (in) "Wireless Disable", 152 SAFE_PWR_REMOVE (1.8V) (out) "Indicate to host that main DC power can be removed", 153 ANT_CNTL0 (1.8V) (out) "Customer-defined external switch control for tunable antennas", 154 ANT_CNTL1 (1.8V) (out) "Customer-defined external switch control for tunable antennas", 155 ANT_CNTL2 (1.8V) (out) "Customer-defined external switch control for tunable antennas", 156 ANT_CNTL3 (1.8V) (out) "Customer-defined external switch control for tunable antennas", 161 SDIO_CMD (2.95V) (out) "SDIO command", 162 SDIO_CLK (2.95V) (out) "SDIO clock", 163 SDIO_DATA_3 (2.95V) (io) "SDIO data bit 3", 164 SDIO_DATA_2 (2.95V) (io) "SDIO data bit 2", 165 SDIO_DATA_1 (2.95V) (io) "SDIO data bit 1", 166 SDIO_DATA_0 (2.95V) (io) "SDIO data bit 0", 236 J1 "Test Point", 237 J2 "Test Point", 238 J3 "Test Point", 239 J4 "Test Point", 240 J5 "Test Point", 241 J6 "Test Point", 242 J7 "Test Point", 243 J8 "Test Point", 244 J9 "Test Point"
part B pins: 10 GPIO2 WUI (1.8V) (io) "General purpose I/O (Wakeup Interrupt)", 24 ADC1 "Analog to Digital Converter", 25 ADC0 "Analog to Digital Converter", 33 PCM_OUT/I2S_OUT (1.8V) (out) "PCM/I2S Data Out", 34 PCM_IN/I2S_IN (1.8V) (in) "PCM/I2S Data In", 35 PCM_SYNC/I2S_WS (1.8V) (io) "PCM Sync/I2S Word Select", 36 PCM_CLK/I2S_CLK (1.8V) (io) "PCM/I2S Clock", 40 GPIO7 (1.8V) (io) "General purpose I/O", 41 GPIO8 (1.8V) (io) "General purpose I/O", 44 GPIO13 (1.8V) (io) "General purpose I/O", 45 VGPIO (1.8V) (out) "GPIO voltage output", 92 GPIO38 SFS WUE (1.8V) (io) "General purpose I/O (SYSFS Wakeup Event)", 93 GPIO39 SFS WUE (1.8V) (io) "General purpose I/O (SYSFS Wakeup Event)", 94 GPIO40 NC/FU (1.8V) (io) "General purpose I/O (Do Not Use/Future Use)", 95 GPIO41 NC/FU (1.8V) (io) "General purpose I/O (Do Not Use/Future Use)", 100 GPIO34 SFS (1.8V) (io) "General purpose I/O (SYSFS)", 101 GPIO35 SFS (1.8V) (io) "General purpose I/O (SYSFS)", 102 GPIO36 SFS WUE (1.8V) (io) "General purpose I/O (SYSFS Wakeup Event)", 103 GPIO37 SFS (1.8V) (io) "General purpose I/O (SYSFS)", 104 GPIO32 (1.8V) (io) "General purpose I/O", 105 GPIO33 (1.8V) (io) "General purpose I/O", 107 ADC2 "Analog to Digital Converter", 108 ADC3 "Analog to Digital Converter", 109 GPIO42 WUI (1.8V) (io) "General purpose I/O (Wakeup Interrupt)", 147 GPIO21 WUI (1.8V) (io) "General purpose I/O (Wakeup Interrupt)", 148 GPIO22 (1.8V) (io) "General purpose I/O", 149 GPIO23 (1.8V) (io) "General purpose I/O", 150 GPIO24 (1.8V) (io) "General purpose I/O", 159 GPIO25 (1.8V) (io) "General purpose I/O"
part C pins: 21 BAT_RTC (power) "Voltage input/Charging output", 61 VBAT_RF (3.7V) (power) "RF power supply", 62 VBAT_RF (3.7V) (power) "RF power supply", 63 VBAT_BB (3.7V) (power) "Baseband power supply", 67 GND (power), 68 GND (power), 69 GND (power), 70 GND (power), 157 VBAT_RF (3.7V) (power) "RF power supply", 158 VBAT_BB (3.7V) (power) "Baseband power supply", 167 GND (power), 168 GND (power), 169 GND (power), 170 GND (power), 171 GND (power), 172 GND (power), 173 GND (power), 174 GND (power), 175 GND (power), 176 GND (power), 177 GND (power), 178 GND (power), 179 GND (power), 180 GND (power), 181 GND (power), 182 GND (power), 183 GND (power), 184 GND (power), 185 GND (power), 186 GND (power), 187 GND (power), 188 GND (power), 189 GND (power), 190 GND (power), 191 GND (power), 192 GND (power), 193 GND (power), 194 GND (power), 195 GND (power), 196 GND (power), 197 GND (power), 198 GND (power), 199 GND (power), 200 GND (power), 201 GND (power), 202 GND (power), 203 GND (power), 204 GND (power), 205 GND (power), 206 GND (power), 207 GND (power), 208 GND (power), 209 GND (power), 210 GND (power), 211 GND (power), 212 GND (power), 213 GND (power), 214 GND (power), 215 GND (power), 216 GND (power), 217 GND (power), 218 GND (power), 219 GND (power), 220 GND (power), 221 GND (power), 222 GND (power), 223 GND (power), 224 GND (power), 225 GND (power), 226 GND (power), 227 GND (power), 228 GND (power), 229 GND (power), 230 GND (power), 231 GND (power), 232 GND (power), 233 GND (power), 234 GND (power)
part D pins: 17 Reserved, 18 Reserved, 19 Reserved, 20 Reserved, 71 Reserved, 72 Reserved, 73 Reserved, 74 Reserved, 75 Reserved, 76 Reserved, 77 Reserved, 78 Reserved, 79 Reserved, 80 Reserved, 81 Reserved, 82 Reserved, 83 Reserved, 84 Reserved, 85 Reserved, 86 Reserved, 87 Reserved, 88 Reserved, 89 Reserved, 90 Reserved, 114 Reserved, 115 Reserved, 116 Reserved, 117 Reserved, 118 Reserved, 119 Reserved, 120 Reserved, 121 Reserved, 122 Reserved, 123 Reserved, 124 Reserved, 129 Reserved, 130 Reserved, 131 Reserved, 132 Reserved, 133 Reserved, 134 Reserved, 135 Reserved, 140 Reserved, 141 Reserved, 142 Reserved, 143 Reserved, 144 Reserved, 145 Reserved, 146 Reserved, 160 Reserved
